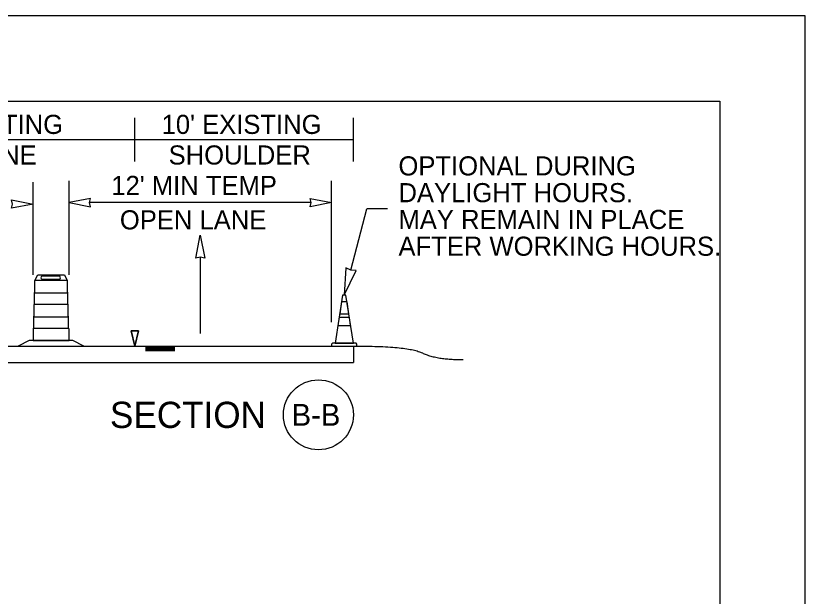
# Model space of a CAD drawing. Extents: x 99999 to 100116, y 99995 to 100013.
# Drawn here: x 100093.175 to 100096.062, y 100008.563 to 100010.687 of the extents above; entities that cross this region are included whole.
import ezdxf

# ---------------------------------------------------------------- set-up
doc = ezdxf.new("R2010")
doc.units = 0
for name, color, linetype in [('SH_GI_PlotLimits', 7, 'Continuous'), ('SH_GI_SheetBorder', 7, 'Continuous'), ('SH_TI_WZSectionCut', 7, 'Continuous'), ('TR_WZ_ArrowLeftStrRightTurn', 7, 'Continuous'), ('TR_WZ_TrafficConeElev', 7, 'Continuous'), ('TR_WZ_TrafficSafetyDrumElev', 7, 'Continuous'), ('TR_WZ_WorkZoneDetails', 7, 'Continuous'), ('TR_WZ_WorkZoneTextCurrent', 7, 'Continuous')]:
    doc.layers.add(name, color=color, linetype=linetype)

msp = doc.modelspace()

# ---------------------------------------------------------------- linework, layer by layer
at = {"layer": 'SH_GI_PlotLimits'}
msp.add_lwpolyline([(100079.0625, 99999.6875), (100096.0625, 99999.6875), (100096.0625, 100010.6875), (100079.0625, 100010.6875)], close=True, dxfattribs=at)
at = {"layer": 'SH_GI_SheetBorder'}
for p, q in [((100080, 100010.375), (100095.75, 100010.375)), ((100095.75, 100010.375), (100095.75, 100000))]:
    msp.add_line(p, q, dxfattribs=at)
at = {"layer": 'SH_TI_WZSectionCut'}
for p, q in [((100093.3698, 100009.7388), (100093.3698, 100010.0836)), ((100094.3298, 100009.5666), (100094.3298, 100010.0836)), ((100094.2548, 100010.0036), (100093.4448, 100010.0036))]:
    msp.add_line(p, q, dxfattribs=at)
for points in [[(100093.3698, 100010.0036), (100093.4484, 100009.9882), (100093.4448, 100010.0036), (100093.4484, 100010.019)], [(100094.3298, 100010.0036), (100094.2512, 100009.9882), (100094.2548, 100010.0036), (100094.2512, 100010.019)]]:
    msp.add_lwpolyline(points, close=True, dxfattribs=at)
at = {"layer": 'TR_WZ_ArrowLeftStrRightTurn'}
msp.add_line((100093.8498, 100009.8039), (100093.8498, 100009.524), dxfattribs=at)
msp.add_lwpolyline([(100093.8498, 100009.884), (100093.8663, 100009.8), (100093.8498, 100009.8039), (100093.8333, 100009.8)], close=True, dxfattribs=at)
at = {"layer": 'TR_WZ_TrafficConeElev'}
for p, q in [((100094.3664, 100009.6404), (100094.3598, 100009.5971)), ((100094.3866, 100009.6404), (100094.3664, 100009.6404)), ((100094.3932, 100009.5971), (100094.3866, 100009.6404)), ((100094.3598, 100009.5971), (100094.3932, 100009.5971)), ((100094.3577, 100009.5837), (100094.3531, 100009.5537)), ((100094.3952, 100009.5837), (100094.3577, 100009.5837)), ((100094.3998, 100009.5537), (100094.3952, 100009.5837)), ((100094.3531, 100009.5537), (100094.3998, 100009.5537)), ((100094.3336, 100009.4887), (100094.3302, 100009.4854)), ((100094.3302, 100009.4854), (100094.3302, 100009.4787)), ((100094.3431, 100009.4887), (100094.3336, 100009.4887)), ((100094.4227, 100009.4854), (100094.4194, 100009.4887)), ((100094.4227, 100009.4787), (100094.4227, 100009.4854)), ((100094.3302, 100009.4787), (100094.4227, 100009.4787))]:
    msp.add_line(p, q, dxfattribs=at)
msp.add_lwpolyline([(100094.3431, 100009.4887), (100094.4098, 100009.4887), (100094.3827, 100009.6654), (100094.3702, 100009.6654)], close=True, dxfattribs=at)
msp.add_lwpolyline([(100094.3431, 100009.4887), (100094.4098, 100009.4887), (100094.3827, 100009.6654), (100094.3702, 100009.6654)], close=True, dxfattribs=at)
msp.add_lwpolyline([(100094.4194, 100009.4887), (100094.4098, 100009.4887), (100094.3431, 100009.4887)], dxfattribs=at)
at = {"layer": 'TR_WZ_TrafficSafetyDrumElev'}
for p, q in [((100093.3631, 100009.7188), (100093.2447, 100009.7188)), ((100093.3631, 100009.7188), (100093.2447, 100009.7188)), ((100093.3355, 100009.734), (100093.2701, 100009.734)), ((100093.2701, 100009.7236), (100093.3355, 100009.7236)), ((100093.3654, 100009.6724), (100093.2424, 100009.6724)), ((100093.2424, 100009.6724), (100093.2424, 100009.6325)), ((100093.3654, 100009.6325), (100093.3654, 100009.6724)), ((100093.2424, 100009.6325), (100093.3654, 100009.6325)), ((100093.3683, 100009.5844), (100093.2395, 100009.5844)), ((100093.2395, 100009.5844), (100093.2395, 100009.5445)), ((100093.3683, 100009.5445), (100093.3683, 100009.5844)), ((100093.2395, 100009.5445), (100093.3683, 100009.5445))]:
    msp.add_line(p, q, dxfattribs=at)
for points in [[(100093.2439, 100009.7172), (100093.2439, 100009.676)], [(100093.2439, 100009.7172), (100093.2439, 100009.676)], [(100093.3639, 100009.676), (100093.3639, 100009.7172)], [(100093.3639, 100009.676), (100093.3639, 100009.7172)], [(100093.2424, 100009.673), (100093.2424, 100009.632)], [(100093.2424, 100009.673), (100093.2424, 100009.632)], [(100093.3654, 100009.632), (100093.3654, 100009.673)], [(100093.3654, 100009.632), (100093.3654, 100009.673)], [(100093.2409, 100009.629), (100093.2409, 100009.5879)], [(100093.2409, 100009.629), (100093.2409, 100009.5879)], [(100093.3669, 100009.5879), (100093.3669, 100009.629)], [(100093.3669, 100009.5879), (100093.3669, 100009.629)], [(100093.2395, 100009.5849), (100093.2395, 100009.5439)], [(100093.2395, 100009.5849), (100093.2395, 100009.5439)], [(100093.3683, 100009.5439), (100093.3683, 100009.5849)], [(100093.3683, 100009.5439), (100093.3683, 100009.5849)], [(100093.238, 100009.5409), (100093.238, 100009.4988), (100093.3698, 100009.4988), (100093.3698, 100009.5409)], [(100093.238, 100009.5409), (100093.238, 100009.4988), (100093.3698, 100009.4988), (100093.3698, 100009.5409)]]:
    msp.add_lwpolyline(points, dxfattribs=at)
for points in [[(100093.2447, 100009.7188), (100093.2552, 100009.7388), (100093.3526, 100009.7388), (100093.3631, 100009.7188)], [(100093.4239, 100009.4788), (100093.3837, 100009.4988), (100093.2241, 100009.4988), (100093.1839, 100009.4788)]]:
    msp.add_lwpolyline(points, close=True, dxfattribs=at)
for centre, major_axis, ratio, start_param, end_param in [((100093.2449, 100009.7168), (0, 0.00199), 0.493438, 0.177149, 1.393647), ((100093.2449, 100009.7168), (0, 0.00199), 0.493438, 0.177149, 1.393647), ((100093.2701, 100009.7288), (0, 0.0052), 0.570305, 6.283185, 9.424778), ((100093.3355, 100009.7288), (0, 0.0052), 0.570305, 3.141593, 6.283185), ((100093.3629, 100009.7168), (0, 0.00199), 0.493438, 4.889538, 6.106036), ((100093.3629, 100009.7168), (0, 0.00199), 0.493438, 4.889538, 6.106036), ((100093.2451, 100009.6705), (0, 0.00606), 0.493438, 0.4288, 1.141997), ((100093.2451, 100009.6705), (0, 0.00606), 0.493438, 0.4288, 1.141997), ((100093.3627, 100009.6705), (0, 0.00606), 0.493438, 5.141189, 5.854386), ((100093.3627, 100009.6705), (0, 0.00606), 0.493438, 5.141189, 5.854386), ((100093.2437, 100009.6265), (0, 0.00606), 0.493438, 0.4288, 1.141997), ((100093.2437, 100009.6265), (0, 0.00606), 0.493438, 0.4288, 1.141997), ((100093.3641, 100009.6265), (0, 0.00606), 0.493438, 5.141189, 5.854386), ((100093.3641, 100009.6265), (0, 0.00606), 0.493438, 5.141189, 5.854386), ((100093.2422, 100009.5824), (0, 0.00606), 0.493438, 0.4288, 1.141997), ((100093.2422, 100009.5824), (0, 0.00606), 0.493438, 0.4288, 1.141997), ((100093.3656, 100009.5824), (0, 0.00606), 0.493438, 5.141189, 5.854386), ((100093.3656, 100009.5824), (0, 0.00606), 0.493438, 5.141189, 5.854386), ((100093.2407, 100009.5384), (0, 0.00606), 0.493438, 0.4288, 1.141997), ((100093.2407, 100009.5384), (0, 0.00606), 0.493438, 0.4288, 1.141997), ((100093.3671, 100009.5384), (0, 0.00606), 0.493438, 5.141189, 5.854386), ((100093.3671, 100009.5384), (0, 0.00606), 0.493438, 5.141189, 5.854386)]:
    msp.add_ellipse(centre, major_axis=major_axis, ratio=ratio, start_param=start_param, end_param=end_param, dxfattribs=at)
at = {"layer": 'TR_WZ_WorkZoneDetails'}
for p, q in [((100093.6098, 100010.154), (100093.6098, 100010.314)), ((100094.4098, 100010.154), (100094.4098, 100010.314)), ((100093.6098, 100010.234), (100092.6498, 100010.234)), ((100094.4098, 100010.234), (100093.6098, 100010.234)), ((100093.238, 100009.7388), (100093.238, 100010.0783)), ((100094.4001, 100009.7561), (100094.4584, 100009.9811)), ((100094.5347, 100009.9811), (100094.4584, 100009.9811)), ((100090.7298, 100009.4787), (100094.4098, 100009.4787)), ((100093.7562, 100009.4746), (100093.6498, 100009.4746)), ((100093.7562, 100009.4701), (100093.6498, 100009.4701)), ((100093.7562, 100009.4655), (100093.6498, 100009.4655)), ((100093.7562, 100009.4614), (100093.6498, 100009.4614)), ((100094.4098, 100009.4787), (100094.4098, 100009.4187)), ((100090.7298, 100009.4187), (100094.4098, 100009.4187))]:
    msp.add_line(p, q, dxfattribs=at)
for points in [[(100093.238, 100009.9983), (100093.1594, 100009.9829), (100093.163, 100009.9983), (100093.1594, 100010.0137)], [(100094.3765, 100009.6654), (100094.4198, 100009.7557), (100094.4, 100009.7561), (100094.3825, 100009.7654)], [(100093.6098, 100009.4787), (100093.6232, 100009.5346), (100093.5965, 100009.5346)]]:
    msp.add_lwpolyline(points, close=True, dxfattribs=at)
msp.add_lwpolyline([(100093.5965, 100009.5346), (100093.6232, 100009.5346), (100093.6098, 100009.4787), (100093.5965, 100009.5346)], dxfattribs=at)
msp.add_circle((100094.2819, 100009.2268), 0.128, dxfattribs=at)
msp.add_open_spline([(100094.4098, 100009.4787), (100094.6108, 100009.4787), (100094.7111, 100009.429), (100094.8115, 100009.429)], degree=2, dxfattribs=at)

# ---------------------------------------------------------------- texts
for s, p in [('EXISTING', (100092.911, 100010.255)), ("10' EXISTING", (100093.7084, 100010.255)), ('LANE', (100093.0068, 100010.143)), ('SHOULDER', (100093.734, 100010.143)), ("12' MIN TEMP", (100093.5244, 100010.0316)), ('OPEN LANE', (100093.5556, 100009.9056))]:
    msp.add_text(s, height=0.07, dxfattribs=at).set_placement(p)
for s, height, p in [('SECTION', 0.096, (100093.5194, 100009.1788)), ('B-B', 0.08, (100094.1839, 100009.1868))]:
    msp.add_text(s, height=height, rotation=360, dxfattribs=at).set_placement(p)
at = {"layer": 'TR_WZ_WorkZoneTextCurrent'}
for s, p in [('OPTIONAL DURING', (100094.5747, 100010.1031)), ('DAYLIGHT HOURS.', (100094.5747, 100010.0051)), ('MAY REMAIN IN PLACE', (100094.5747, 100009.9071)), ('AFTER WORKING HOURS.', (100094.5747, 100009.8091))]:
    msp.add_text(s, height=0.07, dxfattribs=at).set_placement(p)

doc.saveas('drawing.dxf')
